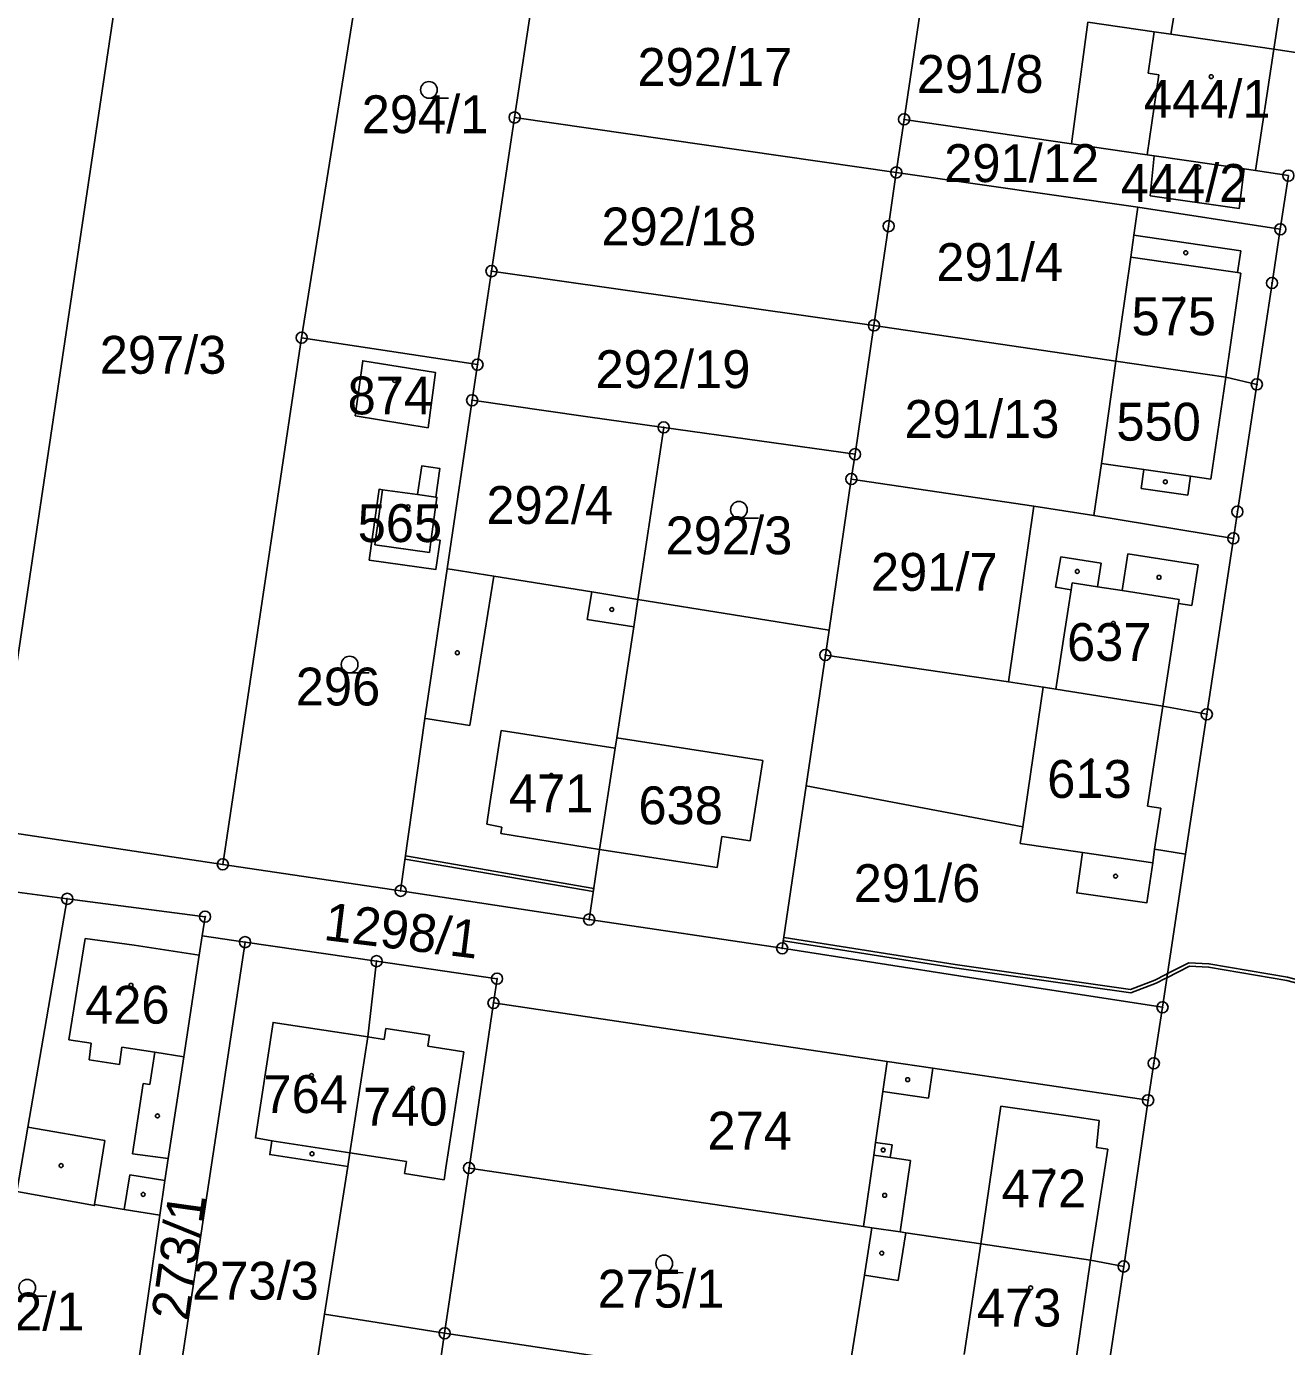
# Model space of a CAD drawing. Extents: x -537341 to -532984, y -1143469 to -1141314.
# Drawn here: x -534482.9 to -534369.7, y -1142935.8 to -1142817.2 of the extents above; entities that cross this region are included whole.
import ezdxf

# ---------------------------------------------------------------- set-up
doc = ezdxf.new("R2010")
doc.units = 0
for name, color, linetype in [('Hranice parcel', 7, 'Continuous'), ('parcelní_č_2000', 7, 'Continuous'), ('Vnitřní kresba', 7, 'Continuous'), ('Věcná břemena k části', 7, 'Continuous'), ('Značky bodu BP', 7, 'Continuous'), ('Značky budov', 7, 'Continuous'), ('Značky kultur', 7, 'Continuous')]:
    doc.layers.add(name, color=color, linetype=linetype)

msp = doc.modelspace()

# ---------------------------------------------------------------- linework, layer by layer
at = {"layer": 'Hranice parcel'}
for p, q in [((-534486, -1142889.32), (-534472.21, -1142797.05)), ((-534450.91, -1142799.74), (-534458.16, -1142845.13)), ((-534436.69, -1142809.73), (-534439.04, -1142825.35)), ((-534402.44, -1142814.64), (-534404.06, -1142825.52)), ((-534387.55, -1142816.8), (-534389.02, -1142827.71)), ((-534439.04, -1142825.35), (-534441.11, -1142839.15)), ((-534439.04, -1142825.35), (-534404.76, -1142830.29)), ((-534404.06, -1142825.52), (-534404.76, -1142830.29)), ((-534404.06, -1142825.52), (-534389.02, -1142827.71)), ((-534381.61, -1142828.79), (-534373.51, -1142829.96)), ((-534383.07, -1142833.4), (-534404.76, -1142830.29)), ((-534370.28, -1142835.39), (-534369.55, -1142830.57)), ((-534370.28, -1142835.39), (-534383.07, -1142833.4)), ((-534441.11, -1142839.15), (-534442.37, -1142847.55)), ((-534441.11, -1142839.15), (-534406.77, -1142844.03)), ((-534406.77, -1142844.03), (-534408.47, -1142855.6)), ((-534406.77, -1142844.03), (-534385.04, -1142847.24)), ((-534458.16, -1142845.13), (-534465.24, -1142892.44)), ((-534458.16, -1142845.13), (-534442.37, -1142847.55)), ((-534442.37, -1142847.55), (-534442.85, -1142850.75)), ((-534442.85, -1142850.75), (-534445.1, -1142865.88)), ((-534425.65, -1142853.19), (-534427.96, -1142868.64)), ((-534408.47, -1142855.6), (-534425.65, -1142853.19)), ((-534408.47, -1142855.6), (-534408.8, -1142857.83)), ((-534408.8, -1142857.83), (-534410.8, -1142871.41)), ((-534392.42, -1142860.26), (-534408.8, -1142857.83)), ((-534392.42, -1142860.26), (-534394.68, -1142876.06)), ((-534387.01, -1142861.1), (-534392.42, -1142860.26)), ((-534387.01, -1142861.1), (-534374.49, -1142863.16)), ((-534376.88, -1142878.96), (-534374.49, -1142863.16)), ((-534410.8, -1142871.41), (-534427.96, -1142868.64)), ((-534411.13, -1142873.64), (-534410.8, -1142871.41)), ((-534411.13, -1142873.64), (-534412.86, -1142885.4)), ((-534394.68, -1142876.06), (-534411.13, -1142873.64)), ((-534378.78, -1142891.52), (-534376.88, -1142878.96)), ((-534415.01, -1142899.98), (-534412.86, -1142885.4)), ((-534465.24, -1142892.44), (-534486, -1142889.32)), ((-534449.27, -1142894.82), (-534465.24, -1142892.44)), ((-534380.86, -1142905.28), (-534378.78, -1142891.52)), ((-534487.41, -1142894.45), (-534479.21, -1142895.54)), ((-534432.34, -1142897.4), (-534449.27, -1142894.82)), ((-534479.21, -1142895.54), (-534466.83, -1142897.14)), ((-534466.83, -1142897.14), (-534467.09, -1142898.87)), ((-534415.01, -1142899.98), (-534432.34, -1142897.4)), ((-534470.03, -1142944.42), (-534463.24, -1142899.43)), ((-534467.36, -1142900.6), (-534467.09, -1142898.87)), ((-534467.09, -1142898.87), (-534463.24, -1142899.43)), ((-534463.24, -1142899.43), (-534451.43, -1142901.14)), ((-534451.43, -1142901.14), (-534452.21, -1142907.94)), ((-534440.93, -1142904.89), (-534443.13, -1142919.72)), ((-534405.57, -1142910.14), (-534440.93, -1142904.89)), ((-534382.15, -1142913.63), (-534384.34, -1142928.56)), ((-534454, -1142919.58), (-534456.11, -1142932.86)), ((-534445.32, -1142934.56), (-534443.13, -1142919.72)), ((-534443.13, -1142919.72), (-534407.71, -1142924.97)), ((-534475.26, -1142953.95), (-534470.9, -1142923.96)), ((-534406.95, -1142925.08), (-534407.71, -1142924.97)), ((-534386.57, -1142943.39), (-534384.34, -1142928.56)), ((-534456.11, -1142932.86), (-534458.16, -1142946.19)), ((-534456.11, -1142932.86), (-534445.32, -1142934.56)), ((-534447.28, -1142947.81), (-534445.32, -1142934.56)), ((-534416.74, -1142938.85), (-534445.32, -1142934.56))]:
    msp.add_line(p, q, dxfattribs=at)
for points in [[(-534387.55, -1142816.8), (-534381.61, -1142817.66), (-534380.11, -1142817.88), (-534370.87, -1142819.22), (-534367.9, -1142819.67)], [(-534389.02, -1142827.71), (-534382.23, -1142828.7), (-534381.61, -1142828.79)], [(-534381.61, -1142828.79), (-534381.96, -1142832.38), (-534373.98, -1142833.53), (-534373.51, -1142829.96)], [(-534404.76, -1142830.29), (-534405.45, -1142835.11), (-534406.77, -1142844.03)], [(-534373.51, -1142829.96), (-534372.52, -1142830.11), (-534369.55, -1142830.57)], [(-534383.07, -1142833.4), (-534383.43, -1142835.92), (-534383.71, -1142837.9), (-534385.04, -1142847.24)], [(-534372.39, -1142849.33), (-534371.02, -1142840.22), (-534370.28, -1142835.39)], [(-534453.35, -1142852.16), (-534452.67, -1142847.21), (-534446.13, -1142848.27), (-534446.81, -1142853.22), (-534453.35, -1142852.16)], [(-534385.04, -1142847.24), (-534386.34, -1142856.42), (-534387.01, -1142861.1)], [(-534372.39, -1142849.33), (-534375.18, -1142848.69), (-534385.04, -1142847.24)], [(-534374.49, -1142863.16), (-534374.13, -1142860.76), (-534372.39, -1142849.33)], [(-534425.65, -1142853.19), (-534432.66, -1142852.22), (-534442.85, -1142850.75)], [(-534452.09, -1142865.12), (-534446.1, -1142865.95), (-534445.73, -1142863.33), (-534446.52, -1142863.22), (-534446.01, -1142859.48), (-534446.12, -1142859.46), (-534445.76, -1142856.87), (-534447.38, -1142856.65), (-534447.75, -1142859.23), (-534450.89, -1142858.79), (-534451.21, -1142858.75), (-534452.09, -1142865.12)], [(-534445.1, -1142865.88), (-534447.11, -1142879.33), (-534449.27, -1142894.82)], [(-534427.96, -1142868.64), (-534432.11, -1142867.97), (-534440.9, -1142866.55), (-534444.63, -1142865.95), (-534445.1, -1142865.88)], [(-534432.34, -1142897.4), (-534431.41, -1142891.11), (-534430.01, -1142882.01), (-534429.87, -1142881.08), (-534428.34, -1142871.1), (-534427.96, -1142868.64)], [(-534376.88, -1142878.96), (-534380.82, -1142878.22), (-534390.43, -1142876.7), (-534390.98, -1142876.62), (-534391.56, -1142876.52), (-534394.68, -1142876.06)], [(-534412.86, -1142885.4), (-534393.41, -1142889.07), (-534393.63, -1142890.56), (-534388.03, -1142891.38), (-534388.56, -1142895), (-534382.27, -1142895.9), (-534381.74, -1142892.31), (-534381.59, -1142891.08), (-534378.78, -1142891.52)], [(-534479.21, -1142895.54), (-534482.74, -1142916.04), (-534483.74, -1142921.82), (-534476.77, -1142923.1), (-534476.75, -1142923), (-534474.1, -1142923.43), (-534470.9, -1142923.96)], [(-534470.9, -1142923.96), (-534470.44, -1142920.84), (-534470.14, -1142918.86), (-534468.73, -1142909.72), (-534467.36, -1142900.6)], [(-534380.86, -1142905.28), (-534398.18, -1142902.59), (-534415.01, -1142899.98)], [(-534451.43, -1142901.14), (-534440.61, -1142902.71), (-534440.93, -1142904.89)], [(-534382.15, -1142913.63), (-534381.64, -1142910.31), (-534380.86, -1142905.28)], [(-534452.21, -1142907.94), (-534460.73, -1142906.64), (-534462.31, -1142917.02), (-534460.83, -1142917.27), (-534461.02, -1142918.51), (-534454, -1142919.58)], [(-534452.21, -1142907.94), (-534453.82, -1142918.35), (-534454, -1142919.58)], [(-534407.71, -1142924.97), (-534406.79, -1142918.56), (-534406.62, -1142917.42), (-534405.96, -1142912.84), (-534405.57, -1142910.14)], [(-534405.57, -1142910.14), (-534401.48, -1142910.75), (-534382.15, -1142913.63)], [(-534406.95, -1142925.08), (-534407.63, -1142929.35), (-534409.31, -1142939.97)], [(-534384.34, -1142928.56), (-534387.31, -1142928), (-534397.17, -1142926.53), (-534403.92, -1142925.53), (-534404.41, -1142925.46), (-534406.95, -1142925.08)]]:
    msp.add_lwpolyline(points, dxfattribs=at)
at = {"layer": 'Vnitřní kresba'}
for p, q in [((-534369.73, -1142811.71), (-534370.87, -1142819.22)), ((-534380.11, -1142817.88), (-534379.29, -1142812.95)), ((-534381.61, -1142817.66), (-534382.14, -1142821.37)), ((-534370.87, -1142819.22), (-534372.52, -1142830.11)), ((-534381.2, -1142821.51), (-534382.23, -1142828.7)), ((-534382.14, -1142821.37), (-534381.2, -1142821.51)), ((-534383.43, -1142835.92), (-534373.82, -1142837.32)), ((-534383.71, -1142837.9), (-534374.13, -1142839.28)), ((-534373.82, -1142837.32), (-534374.13, -1142839.28)), ((-534373.81, -1142839.33), (-534375.18, -1142848.69)), ((-534374.13, -1142839.28), (-534373.81, -1142839.33)), ((-534375.18, -1142848.69), (-534376.51, -1142857.85)), ((-534382.54, -1142856.97), (-534386.34, -1142856.42)), ((-534382.77, -1142858.67), (-534382.54, -1142856.97)), ((-534382.54, -1142856.97), (-534378.34, -1142857.58)), ((-534378.34, -1142857.58), (-534378.59, -1142859.28)), ((-534376.51, -1142857.85), (-534378.34, -1142857.58)), ((-534450.89, -1142858.79), (-534451.58, -1142863.74)), ((-534447.75, -1142859.23), (-534446.12, -1142859.46)), ((-534378.59, -1142859.28), (-534382.77, -1142858.67)), ((-534451.58, -1142863.74), (-534446.68, -1142864.43)), ((-534446.68, -1142864.43), (-534446.52, -1142863.22)), ((-534390.46, -1142867.54), (-534389.99, -1142864.82)), ((-534389.99, -1142864.82), (-534386.37, -1142865.38)), ((-534384.48, -1142867.85), (-534383.97, -1142864.56)), ((-534383.97, -1142864.56), (-534377.65, -1142865.55)), ((-534386.37, -1142865.38), (-534386.69, -1142867.51)), ((-534377.65, -1142865.55), (-534378.21, -1142869.2)), ((-534443.07, -1142879.96), (-534440.9, -1142866.55)), ((-534389.06, -1142867.78), (-534390.46, -1142867.54)), ((-534389.06, -1142867.78), (-534388.97, -1142867.16)), ((-534388.97, -1142867.16), (-534386.69, -1142867.51)), ((-534386.69, -1142867.51), (-534384.48, -1142867.85)), ((-534432.11, -1142867.97), (-534432.51, -1142870.44)), ((-534389.33, -1142869.53), (-534389.06, -1142867.78)), ((-534384.48, -1142867.85), (-534379.35, -1142868.64)), ((-534379.35, -1142868.64), (-534379.41, -1142869.02)), ((-534389.68, -1142871.83), (-534389.33, -1142869.53)), ((-534379.41, -1142869.02), (-534380.11, -1142873.56)), ((-534378.21, -1142869.2), (-534379.41, -1142869.02)), ((-534432.51, -1142870.44), (-534428.34, -1142871.1)), ((-534390.43, -1142876.7), (-534389.68, -1142871.83)), ((-534380.11, -1142873.56), (-534380.82, -1142878.22)), ((-534391.56, -1142876.52), (-534393.41, -1142889.07)), ((-534380.82, -1142878.22), (-534382.21, -1142887.21)), ((-534447.11, -1142879.33), (-534446.82, -1142879.37)), ((-534446.82, -1142879.37), (-534443.07, -1142879.96)), ((-534441.29, -1142887.18), (-534440.25, -1142880.41)), ((-534440.25, -1142880.41), (-534430.01, -1142882.01)), ((-534429.87, -1142881.08), (-534416.76, -1142883.11)), ((-534416.76, -1142883.11), (-534417.87, -1142890.34)), ((-534441.54, -1142888.82), (-534441.29, -1142887.18)), ((-534382.21, -1142887.21), (-534381.02, -1142887.4)), ((-534381.02, -1142887.4), (-534381.59, -1142891.08)), ((-534440.19, -1142889.09), (-534441.54, -1142888.82)), ((-534440.27, -1142889.67), (-534440.19, -1142889.09)), ((-534431.41, -1142891.11), (-534440.27, -1142889.67)), ((-534420.44, -1142889.94), (-534420.86, -1142892.73)), ((-534417.87, -1142890.34), (-534420.44, -1142889.94)), ((-534420.86, -1142892.73), (-534431.41, -1142891.11)), ((-534388.03, -1142891.38), (-534381.74, -1142892.31)), ((-534477.61, -1142899.09), (-534479.07, -1142908.2)), ((-534473.21, -1142899.71), (-534477.61, -1142899.09)), ((-534467.36, -1142900.6), (-534473.21, -1142899.71)), ((-534450.76, -1142908.16), (-534450.61, -1142907.18)), ((-534450.61, -1142907.18), (-534446.68, -1142907.79)), ((-534446.68, -1142907.79), (-534446.83, -1142908.77)), ((-534479.07, -1142908.2), (-534477.05, -1142908.5)), ((-534477.05, -1142908.5), (-534477.23, -1142910.01)), ((-534474.52, -1142910.43), (-534474.3, -1142908.87)), ((-534474.3, -1142908.87), (-534471.33, -1142909.32)), ((-534452.21, -1142907.94), (-534450.76, -1142908.16)), ((-534446.83, -1142908.77), (-534443.59, -1142909.27)), ((-534477.23, -1142910.01), (-534474.52, -1142910.43)), ((-534471.33, -1142909.32), (-534471.78, -1142912.23)), ((-534471.33, -1142909.32), (-534468.73, -1142909.72)), ((-534443.59, -1142909.27), (-534445.2, -1142919.69)), ((-534401.87, -1142913.43), (-534401.48, -1142910.75)), ((-534472.39, -1142912.13), (-534473.36, -1142918.45)), ((-534471.78, -1142912.23), (-534472.39, -1142912.13)), ((-534405.96, -1142912.84), (-534401.87, -1142913.43)), ((-534397.17, -1142926.53), (-534395.38, -1142914.15)), ((-534395.38, -1142914.15), (-534388.91, -1142915.09)), ((-534482.74, -1142916.04), (-534475.83, -1142917.25)), ((-534388.91, -1142915.09), (-534386.53, -1142915.44)), ((-534386.53, -1142915.44), (-534386.79, -1142917.89)), ((-534475.83, -1142917.25), (-534476.75, -1142923)), ((-534460.83, -1142917.27), (-534453.82, -1142918.35)), ((-534473.36, -1142918.45), (-534470.14, -1142918.86)), ((-534448.74, -1142919.14), (-534453.82, -1142918.35)), ((-534406.79, -1142918.56), (-534405.31, -1142918.77)), ((-534405.14, -1142917.64), (-534406.62, -1142917.42)), ((-534405.31, -1142918.77), (-534405.14, -1142917.64)), ((-534385.77, -1142918.04), (-534387.31, -1142928)), ((-534386.79, -1142917.89), (-534385.77, -1142918.04)), ((-534448.91, -1142920.22), (-534448.74, -1142919.14)), ((-534445.2, -1142919.69), (-534445.37, -1142920.77)), ((-534403.48, -1142919.03), (-534405.31, -1142918.77)), ((-534404.41, -1142925.46), (-534403.48, -1142919.03)), ((-534474.1, -1142923.43), (-534473.59, -1142920.32)), ((-534473.59, -1142920.32), (-534470.44, -1142920.84)), ((-534445.37, -1142920.77), (-534448.91, -1142920.22)), ((-534403.92, -1142925.53), (-534404.6, -1142929.83)), ((-534398.66, -1142936.46), (-534397.17, -1142926.53)), ((-534387.31, -1142928), (-534388.75, -1142937.92)), ((-534404.6, -1142929.83), (-534407.63, -1142929.35))]:
    msp.add_line(p, q, dxfattribs=at)
at = {"layer": 'Věcná břemena k části'}
for points in [[(-534448.83, -1142891.67), (-534448.87, -1142891.97), (-534431.97, -1142894.89), (-534431.93, -1142894.6)], [(-534414.86, -1142898.99), (-534414.91, -1142899.3), (-534414.9, -1142899.3), (-534399.53, -1142901.74), (-534383.69, -1142903.98), (-534381.42, -1142903.11), (-534380.63, -1142902.7), (-534380.46, -1142902.62), (-534380.4, -1142902.25), (-534380.57, -1142902.34), (-534381.54, -1142902.83), (-534383.73, -1142903.67), (-534399.48, -1142901.44), (-534414.82, -1142899.01)], [(-534364.74, -1142904.75), (-534365.08, -1142904.69), (-534366.94, -1142903.29), (-534369.63, -1142902.57), (-534376.69, -1142901.37), (-534378.5, -1142901.28), (-534380.4, -1142902.25), (-534380.46, -1142902.62), (-534378.43, -1142901.58), (-534376.72, -1142901.67), (-534369.69, -1142902.87), (-534367.07, -1142903.56), (-534365.2, -1142904.97), (-534364.78, -1142905.05), (-534363.95, -1142905.2), (-534363.25, -1142904.88), (-534363.17, -1142904.44), (-534364.48, -1142904.2), (-534364.59, -1142904.78)]]:
    msp.add_lwpolyline(points, close=True, dxfattribs=at)
at = {"layer": 'Značky bodu BP'}
for centre, radius in [((-534439.04, -1142825.35), 0.5), ((-534439.04, -1142825.35), 0.0303), ((-534404.06, -1142825.52), 0.5), ((-534404.06, -1142825.52), 0.0303), ((-534404.76, -1142830.29), 0.5), ((-534404.76, -1142830.29), 0.0303), ((-534369.55, -1142830.57), 0.5), ((-534405.45, -1142835.11), 0.5), ((-534405.45, -1142835.11), 0.0303), ((-534370.28, -1142835.39), 0.5), ((-534370.28, -1142835.39), 0.0303), ((-534441.11, -1142839.15), 0.5), ((-534441.11, -1142839.15), 0.0303), ((-534371.02, -1142840.22), 0.5), ((-534371.02, -1142840.22), 0.0303), ((-534406.77, -1142844.03), 0.5), ((-534458.16, -1142845.13), 0.5), ((-534406.77, -1142844.03), 0.0303), ((-534458.16, -1142845.13), 0.0303), ((-534442.37, -1142847.55), 0.5), ((-534442.37, -1142847.55), 0.0303), ((-534372.39, -1142849.33), 0.5), ((-534372.39, -1142849.33), 0.0303), ((-534442.85, -1142850.75), 0.5), ((-534442.85, -1142850.75), 0.0303), ((-534425.65, -1142853.19), 0.5), ((-534425.65, -1142853.19), 0.0303), ((-534408.47, -1142855.6), 0.5), ((-534408.47, -1142855.6), 0.0303), ((-534408.8, -1142857.83), 0.5), ((-534408.8, -1142857.83), 0.0303), ((-534374.13, -1142860.76), 0.5), ((-534374.13, -1142860.76), 0.0303), ((-534374.49, -1142863.16), 0.5), ((-534374.49, -1142863.16), 0.0303), ((-534411.13, -1142873.64), 0.5), ((-534411.13, -1142873.64), 0.0303), ((-534376.88, -1142878.96), 0.5), ((-534376.88, -1142878.96), 0.0303), ((-534465.24, -1142892.44), 0.5), ((-534465.24, -1142892.44), 0.0303), ((-534449.27, -1142894.82), 0.5), ((-534449.27, -1142894.82), 0.0303), ((-534479.21, -1142895.54), 0.5), ((-534479.21, -1142895.54), 0.0303), ((-534466.83, -1142897.14), 0.5), ((-534466.83, -1142897.14), 0.0303), ((-534432.34, -1142897.4), 0.5), ((-534432.34, -1142897.4), 0.0303), ((-534463.24, -1142899.43), 0.5), ((-534463.24, -1142899.43), 0.0303), ((-534415.01, -1142899.98), 0.5), ((-534451.43, -1142901.14), 0.5), ((-534415.01, -1142899.98), 0.0303), ((-534451.43, -1142901.14), 0.0303), ((-534440.61, -1142902.71), 0.5), ((-534440.61, -1142902.71), 0.0303), ((-534440.93, -1142904.89), 0.5), ((-534440.93, -1142904.89), 0.0303), ((-534380.86, -1142905.28), 0.5), ((-534380.86, -1142905.28), 0.0303), ((-534381.64, -1142910.31), 0.5), ((-534381.64, -1142910.31), 0.0303), ((-534382.15, -1142913.63), 0.5), ((-534382.15, -1142913.63), 0.0303), ((-534443.13, -1142919.72), 0.5), ((-534443.13, -1142919.72), 0.0303), ((-534384.34, -1142928.56), 0.5), ((-534384.34, -1142928.56), 0.0303), ((-534445.32, -1142934.56), 0.5), ((-534445.32, -1142934.56), 0.0303)]:
    msp.add_circle(centre, radius, dxfattribs=at)
at = {"layer": 'Značky budov'}
for centre in [(-534376.48, -1142821.68), (-534377.61, -1142829.81), (-534378.77, -1142837.5), (-534379.1, -1142841.66), (-534449.81, -1142848.97), (-534380.46, -1142851.12), (-534380.6, -1142858.08), (-534448.61, -1142860.33), (-534388.51, -1142866.13), (-534381.17, -1142866.66), (-534430.31, -1142869.55), (-534385.27, -1142870.8), (-534444.18, -1142873.43), (-534387.26, -1142883.14), (-534435.74, -1142884.45), (-534423.53, -1142885.67), (-534385.07, -1142893.5), (-534473.48, -1142903.31), (-534457.28, -1142911.41), (-534448.21, -1142912.56), (-534403.74, -1142911.78), (-534471.11, -1142915.04), (-534457.23, -1142918.44), (-534405.94, -1142918.1), (-534479.76, -1142919.5), (-534390.87, -1142919.98), (-534472.39, -1142922.09), (-534405.81, -1142922.17), (-534406.07, -1142927.37), (-534392.7, -1142930.49)]:
    msp.add_circle(centre, 0.175, dxfattribs=at)
at = {"layer": 'Značky kultur'}
for p, q in [((-534446.73, -1142823.62), (-534444.98, -1142823.62)), ((-534418.89, -1142861.34), (-534417.14, -1142861.34)), ((-534453.85, -1142875.24), (-534452.1, -1142875.24)), ((-534425.64, -1142929.04), (-534423.9, -1142929.13)), ((-534482.8, -1142931.22), (-534481.05, -1142931.22))]:
    msp.add_line(p, q, dxfattribs=at)
for centre in [(-534446.73, -1142822.87), (-534418.89, -1142860.59), (-534453.85, -1142874.49), (-534425.6, -1142928.29), (-534482.8, -1142930.47)]:
    msp.add_circle(centre, 0.75, dxfattribs=at)

# ---------------------------------------------------------------- texts
at = {"layer": 'parcelní_č_2000'}
for s, p in [('292/17', (-534428, -1142822.51)), ('291/8', (-534402.92, -1142823.14)), ('444/1', (-534382.53, -1142825.38)), ('294/1', (-534452.77, -1142826.76)), ('291/12', (-534400.46, -1142831.15)), ('444/2', (-534384.61, -1142832.93)), ('292/18', (-534431.24, -1142836.84)), ('291/4', (-534401.17, -1142840.04)), ('575', (-534383.64, -1142844.91)), ('297/3', (-534476.29, -1142848.37)), ('292/19', (-534431.77, -1142849.66)), ('874', (-534454.03, -1142852.02)), ('291/13', (-534404.02, -1142854.13)), ('550', (-534385, -1142854.38)), ('292/4', (-534441.57, -1142861.86)), ('565', (-534453.13, -1142863.49)), ('292/3', (-534425.48, -1142864.59)), ('291/7', (-534407.04, -1142867.87)), ('637', (-534389.43, -1142874.17)), ('296', (-534458.69, -1142878.17)), ('613', (-534391.21, -1142886.47)), ('471', (-534439.55, -1142887.76)), ('638', (-534427.92, -1142888.84)), ('291/6', (-534408.59, -1142895.83)), ('426', (-534477.61, -1142906.75)), ('764', (-534461.59, -1142914.78)), ('740', (-534452.64, -1142915.91)), ('274', (-534421.72, -1142918.06)), ('472', (-534395.3, -1142923.26)), ('273/3', (-534468, -1142931.54)), ('275/1', (-534431.58, -1142932.26)), ('272/1', (-534489.04, -1142934.31)), ('473', (-534397.53, -1142933.96))]:
    msp.add_text(s, height=3.4, dxfattribs=at).set_placement(p)
for s, rotation, p in [('1298/1', 353, (-534456.27, -1142899.22)), ('273/1', 82, (-534468.31, -1142933.55))]:
    msp.add_text(s, height=3.4, rotation=rotation, dxfattribs=at).set_placement(p)

doc.saveas('drawing.dxf')
